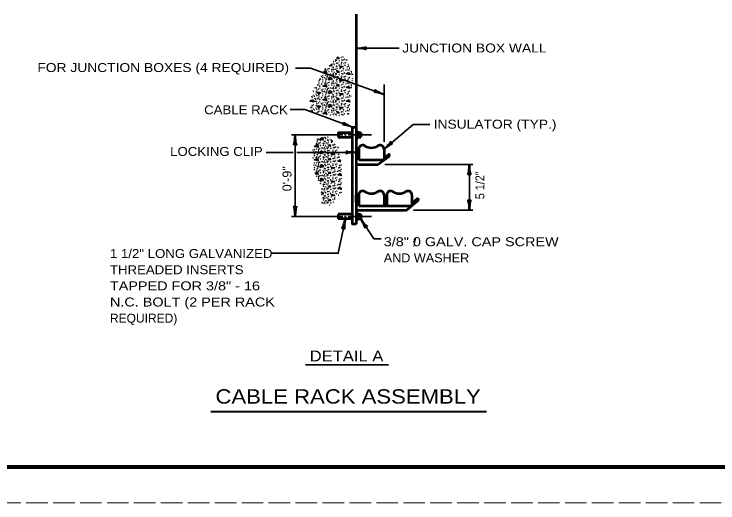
# Model space of a CAD drawing. Extents: x 788 to 1469, y -1 to 439.
# Drawn here: x 1076.7 to 1272.6, y -1 to 135.2 of the extents above; entities that cross this region are included whole.
import ezdxf

# ---------------------------------------------------------------- set-up
doc = ezdxf.new("R2010")
doc.units = 0
doc.linetypes.add('LONG_DASHED', pattern=[7.5, 6, -1.5])
doc.layers.add('1', color=7, linetype='Continuous', lineweight=35)
doc.layers.add('61', color=7, linetype='Continuous', lineweight=35)

msp = doc.modelspace()

# ---------------------------------------------------------------- linework, layer by layer
at = {"layer": '1', "lineweight": 53}
for p, q in [((1171.893, 135.206), (1171.893, 103.706)), ((1166.893, 102.206), (1170.893, 102.206)), ((1166.893, 102.206), (1166.893, 100.956)), ((1171.893, 103.706), (1171.893, 94.98)), ((1171.893, 102.581), (1172.393, 102.581)), ((1172.393, 102.581), (1172.393, 100.581)), ((1172.393, 102.206), (1173.143, 102.206)), ((1173.143, 102.206), (1173.143, 100.956)), ((1166.893, 100.956), (1170.893, 100.956)), ((1171.893, 100.581), (1172.393, 100.581)), ((1172.393, 100.956), (1173.143, 100.956)), ((1172.643, 97.581), (1172.643, 94.581)), ((1179.643, 97.581), (1179.643, 94.581)), ((1171.893, 95.581), (1171.893, 82.831)), ((1172.643, 94.581), (1179.643, 94.581)), ((1177.893, 93.331), (1181.271, 95.743)), ((1171.893, 93.331), (1177.893, 93.331)), ((1172.643, 84.831), (1172.643, 81.831)), ((1179.643, 84.831), (1179.643, 81.831)), ((1180.393, 84.831), (1180.393, 81.831)), ((1187.393, 84.831), (1187.393, 81.831)), ((1171.893, 82.831), (1171.893, 76.706)), ((1179.643, 82.581), (1180.393, 82.581)), ((1170.893, 79.456), (1166.893, 79.456)), ((1166.893, 79.456), (1166.893, 78.206)), ((1172.393, 79.831), (1171.893, 79.831)), ((1172.393, 79.831), (1172.393, 77.831)), ((1172.393, 79.456), (1173.143, 79.456)), ((1173.143, 79.456), (1173.143, 78.206)), ((1170.893, 78.206), (1166.893, 78.206)), ((1172.393, 77.831), (1171.893, 77.831)), ((1172.393, 78.206), (1173.143, 78.206))]:
    msp.add_line(p, q, dxfattribs=at)
at = {"layer": '1'}
for p, q in [((1171.893, 125.706), (1183.893, 125.706)), ((1161.461, 116.472), (1161.461, 116.472)), ((1179.643, 99.581), (1179.643, 115.581)), ((1169.821, 107.532), (1169.381, 107.292)), ((1169.881, 107.397), (1169.781, 107.552)), ((1153.893, 101.581), (1168.143, 101.581)), ((1154.893, 101.581), (1154.893, 78.831)), ((1164.826, 100.12), (1165.152, 100.083)), ((1168.643, 101.581), (1169.143, 101.581)), ((1169.643, 101.581), (1176.143, 101.581)), ((1154.393, 96.686), (1146.825, 96.686)), ((1171.893, 96.686), (1155.393, 96.686)), ((1167.569, 94.327), (1167.406, 94.581)), ((1179.893, 93.331), (1204.393, 93.331)), ((1203.393, 93.331), (1203.393, 80.581)), ((1161.186, 91.141), (1160.426, 90.833)), ((1187.893, 80.581), (1204.393, 80.581)), ((1153.893, 78.831), (1168.143, 78.831)), ((1168.643, 78.831), (1169.143, 78.831)), ((1169.643, 78.831), (1176.143, 78.831)), ((1157.769, 37.483), (1180.923, 37.483))]:
    msp.add_line(p, q, dxfattribs=at)
at = {"layer": '1', "lineweight": 40}
msp.add_line((1131.448, 24.479), (1208.207, 24.479), dxfattribs=at)
at = {"layer": '1'}
for points in [[(1166.921, 123.252), (1166.541, 122.852), (1167.121, 122.812), (1166.921, 123.212)], [(1169.31, 122.453), (1169.161, 122.372), (1169.39, 122.33)], [(1179.643, 112.819), (1159.152, 120.163), (1155.011, 120.163)], [(1164.854, 121.236), (1165.141, 121.072), (1164.363, 120.691)], [(1163.561, 119.312), (1162.621, 118.932), (1163.661, 118.812), (1163.561, 119.272)], [(1164.441, 117.672), (1165.141, 117.272), (1164.281, 116.852), (1164.401, 117.692)], [(1166.921, 119.452), (1166.541, 119.052), (1167.121, 119.012), (1166.921, 119.412)], [(1169.821, 118.932), (1169.161, 118.572), (1170.141, 118.392), (1169.781, 118.952)], [(1161.708, 117.172), (1162.001, 117.112), (1161.496, 116.57)], [(1166.921, 115.652), (1166.541, 115.252), (1167.121, 115.212), (1166.921, 115.612)], [(1163.561, 115.512), (1162.621, 115.132), (1163.661, 115.012), (1163.561, 115.472)], [(1164.441, 113.872), (1165.141, 113.472), (1164.281, 113.052), (1164.401, 113.892)], [(1169.821, 115.132), (1169.161, 114.772), (1170.141, 114.592), (1169.781, 115.152)], [(1161.461, 112.672), (1161.221, 113.472), (1162.001, 113.312), (1161.441, 112.712)], [(1163.561, 111.712), (1162.621, 111.332), (1163.661, 111.212), (1163.561, 111.672)], [(1166.921, 111.852), (1166.541, 111.452), (1167.121, 111.412), (1166.921, 111.812)], [(1159.741, 111.332), (1159.081, 110.972), (1160.061, 110.792), (1159.701, 111.352)], [(1164.441, 110.072), (1165.141, 109.672), (1164.281, 109.252), (1164.401, 110.092)], [(1169.821, 111.332), (1169.161, 110.972), (1170.141, 110.792), (1169.781, 111.352)], [(1170.893, 103.706), (1157.61, 108.629), (1153.469, 108.629)], [(1161.461, 108.872), (1161.221, 109.672), (1162.001, 109.512), (1161.441, 108.912)], [(1163.561, 107.912), (1162.621, 107.532), (1163.661, 107.412), (1163.561, 107.872)], [(1166.921, 108.052), (1166.541, 107.652), (1167.121, 107.612), (1166.921, 108.012)], [(1179.643, 97.581), (1187.734, 104.486), (1192.363, 104.486)], [(1162.274, 100.782), (1162.766, 100.501), (1161.906, 100.081), (1161.996, 100.71)], [(1165.417, 99.842), (1165.186, 99.76), (1164.826, 100.12)], [(1161.186, 98.74), (1160.246, 98.361), (1161.286, 98.24), (1161.186, 98.7)], [(1164.546, 98.88), (1164.166, 98.48), (1164.746, 98.441), (1164.546, 98.84)], [(1166.96, 98.095), (1166.786, 98.001), (1166.981, 97.965)], [(1159.578, 96.55), (1159.626, 96.54), (1159.571, 96.481)], [(1162.066, 97.1), (1162.766, 96.7), (1161.906, 96.281), (1162.026, 97.12)], [(1161.186, 94.941), (1160.246, 94.56), (1161.286, 94.441), (1161.186, 94.9)], [(1164.546, 95.081), (1164.166, 94.68), (1164.746, 94.641), (1164.546, 95.04)], [(1167.446, 94.56), (1166.786, 94.2), (1167.614, 94.048)], [(1162.066, 93.3), (1162.766, 92.9), (1161.906, 92.48), (1162.026, 93.32)], [(1160.473, 90.734), (1161.286, 90.641), (1161.186, 91.1)], [(1164.546, 91.281), (1164.166, 90.88), (1164.746, 90.84), (1164.546, 91.24)], [(1167.446, 90.76), (1166.786, 90.4), (1167.766, 90.221), (1167.406, 90.781)], [(1162.066, 89.501), (1162.766, 89.1), (1161.906, 88.68), (1162.026, 89.52)], [(1164.546, 87.48), (1164.166, 87.081), (1164.746, 87.04), (1164.546, 87.441)], [(1167.446, 86.96), (1166.786, 86.6), (1167.766, 86.421), (1167.406, 86.98)], [(1162.115, 85.673), (1162.766, 85.3), (1162.102, 84.976)], [(1164.546, 83.68), (1164.166, 83.281), (1164.746, 83.24), (1164.546, 83.641)], [(1168.885, 78.206), (1166.887, 68.566), (1148.331, 68.566)], [(1173.143, 78.206), (1176.809, 72.616), (1178.815, 72.616)]]:
    msp.add_lwpolyline(points, dxfattribs=at)
for points in [[(1167.201, 120.692), (1168.241, 120.572), (1167.561, 120.332)], [(1167.201, 116.892), (1168.241, 116.772), (1167.561, 116.532)], [(1167.201, 113.092), (1168.241, 112.972), (1167.561, 112.732)], [(1167.201, 109.292), (1168.241, 109.172), (1167.561, 108.932)], [(1164.826, 96.32), (1165.866, 96.2), (1165.186, 95.96)], [(1171.893, 95.581), (1171.893, 97.581), (1172.643, 97.581), (1172.643, 95.581)], [(1164.826, 92.52), (1165.866, 92.4), (1165.186, 92.16)], [(1164.826, 88.721), (1165.866, 88.6), (1165.186, 88.361)], [(1164.826, 84.921), (1165.866, 84.8), (1165.186, 84.56)]]:
    msp.add_lwpolyline(points, close=True, dxfattribs=at)
at = {"layer": '1', "lineweight": 53}
for points in [[(1171.893, 76.706), (1170.893, 76.706), (1170.893, 103.706), (1171.893, 103.706)], [(1179.643, 95.195), (1180.98, 96.15), (1181.271, 95.743)], [(1171.893, 80.581), (1185.893, 80.581), (1189.314, 83.431)], [(1187.393, 82.482), (1188.994, 83.815), (1189.314, 83.431)], [(1172.643, 81.831), (1179.643, 81.831), (1187.393, 81.831)]]:
    msp.add_lwpolyline(points, dxfattribs=at)
msp.add_lwpolyline([(1171.893, 84.831), (1172.643, 84.831), (1172.643, 82.831), (1171.893, 82.831)], close=True, dxfattribs=at)
at = {"layer": '1'}
for centre in [(1165.611, 122.01), (1166.194, 122.421), (1166.208, 122.102), (1166.367, 121.506), (1166.427, 122.341), (1166.785, 121.559), (1167.209, 122.169), (1167.819, 123.11), (1167.845, 121.665), (1167.925, 122.394), (1168.27, 123.282), (1168.27, 122.354), (1168.588, 122.593), (1168.932, 121.665), (1163.159, 119.602), (1163.372, 119.915), (1163.796, 119.562), (1164.074, 119.888), (1164.352, 120.008), (1165.094, 120.724), (1165.121, 119.655), (1165.134, 119.822), (1165.426, 120.326), (1165.558, 121.453), (1165.624, 119.708), (1165.651, 120.326), (1165.784, 121.161), (1166.115, 119.835), (1166.347, 120.695), (1166.48, 119.522), (1166.573, 120.71), (1166.573, 120.114), (1167.116, 121.042), (1167.382, 120.074), (1167.792, 121.267), (1168.376, 119.995), (1168.535, 121.453), (1168.813, 120.936), (1169.078, 119.575), (1169.409, 120.525), (1169.476, 119.769), (1169.688, 121.161), (1169.727, 120.671), (1169.873, 119.641), (1170.072, 120.127), (1162.232, 117.865), (1162.643, 118.09), (1163.292, 118.183), (1163.69, 118.674), (1163.756, 117.547), (1163.822, 117.852), (1163.928, 118.17), (1164.206, 118.342), (1164.326, 119.191), (1164.737, 118.462), (1165.161, 119.204), (1165.187, 118.316), (1165.505, 118.607), (1165.558, 117.653), (1165.611, 118.21), (1165.837, 119.018), (1166.194, 118.621), (1166.208, 118.302), (1166.367, 117.706), (1166.427, 118.541), (1166.785, 117.759), (1167.209, 118.369), (1167.819, 119.31), (1167.845, 117.865), (1167.925, 118.594), (1168.27, 119.482), (1168.27, 118.554), (1168.535, 117.653), (1168.588, 118.793), (1168.932, 117.865), (1170.496, 119.244), (1170.496, 118.501), (1170.655, 119.032), (1170.88, 118.409), (1161.49, 115.603), (1161.582, 116.128), (1162.271, 115.709), (1162.51, 117.494), (1162.603, 116.34), (1162.669, 116.884), (1163.027, 117.467), (1163.159, 115.802), (1163.372, 116.115), (1163.451, 117.136), (1163.464, 116.619), (1163.743, 117.07), (1163.796, 115.762), (1164.074, 116.088), (1164.352, 116.208), (1165.094, 116.924), (1165.121, 115.855), (1165.134, 116.022), (1165.426, 116.526), (1165.624, 115.908), (1165.651, 116.526), (1165.784, 117.361), (1166.115, 116.035), (1166.347, 116.895), (1166.48, 115.722), (1166.573, 116.91), (1166.573, 116.314), (1167.116, 117.242), (1167.382, 116.274), (1167.792, 117.467), (1168.27, 115.682), (1168.376, 116.195), (1168.813, 117.136), (1169.078, 115.775), (1169.409, 116.725), (1169.476, 115.969), (1169.688, 117.361), (1169.727, 116.871), (1169.873, 115.841), (1170.072, 116.327), (1170.098, 117.534), (1170.43, 116.128), (1160.018, 113.734), (1160.8, 114.609), (1160.92, 114.038), (1161.463, 114.277), (1161.715, 115.139), (1161.768, 115.139), (1161.834, 114.555), (1162.232, 114.065), (1162.51, 113.694), (1162.643, 114.29), (1163.027, 113.667), (1163.292, 114.383), (1163.69, 114.874), (1163.756, 113.747), (1163.822, 114.052), (1163.928, 114.37), (1164.206, 114.542), (1164.326, 115.391), (1164.737, 114.662), (1165.161, 115.404), (1165.187, 114.516), (1165.505, 114.807), (1165.558, 113.853), (1165.611, 114.41), (1165.837, 115.218), (1166.194, 114.821), (1166.208, 114.502), (1166.367, 113.906), (1166.427, 114.741), (1166.785, 113.959), (1167.209, 114.569), (1167.792, 113.667), (1167.819, 115.51), (1167.845, 114.065), (1167.925, 114.794), (1168.27, 114.754), (1168.535, 113.853), (1168.588, 114.993), (1168.932, 114.065), (1170.098, 113.734), (1170.496, 115.444), (1170.496, 114.701), (1170.655, 115.232), (1159.793, 112.041), (1159.992, 112.527), (1160.35, 112.328), (1160.747, 112.898), (1160.787, 113.495), (1160.933, 112.474), (1161.49, 111.803), (1161.582, 112.328), (1162.271, 111.909), (1162.603, 112.54), (1162.669, 113.084), (1163.159, 112.002), (1163.372, 112.315), (1163.451, 113.336), (1163.464, 112.819), (1163.743, 113.27), (1163.796, 111.962), (1164.074, 112.288), (1164.352, 112.408), (1165.094, 113.124), (1165.121, 112.055), (1165.134, 112.222), (1165.426, 112.726), (1165.624, 112.108), (1165.651, 112.726), (1165.784, 113.561), (1166.115, 112.235), (1166.347, 113.095), (1166.48, 111.922), (1166.573, 113.11), (1166.573, 112.514), (1167.116, 113.442), (1167.382, 112.474), (1167.819, 111.71), (1168.27, 111.882), (1168.376, 112.395), (1168.813, 113.336), (1169.078, 111.975), (1169.409, 112.925), (1169.476, 112.169), (1169.688, 113.561), (1169.727, 113.071), (1169.873, 112.041), (1170.072, 112.527), (1170.43, 112.328), (1159.608, 109.761), (1160.018, 109.934), (1160.416, 111.644), (1160.416, 110.901), (1160.575, 111.432), (1160.8, 110.809), (1160.92, 110.238), (1161.092, 111.644), (1161.463, 110.477), (1161.715, 111.339), (1161.768, 111.339), (1161.834, 110.755), (1162.232, 110.265), (1162.51, 109.894), (1162.643, 110.49), (1163.027, 109.867), (1163.292, 110.583), (1163.69, 111.074), (1163.756, 109.947), (1163.822, 110.252), (1163.928, 110.57), (1164.206, 110.742), (1164.326, 111.591), (1164.737, 110.862), (1165.161, 111.604), (1165.187, 110.716), (1165.505, 111.007), (1165.558, 110.053), (1165.611, 110.61), (1165.784, 109.761), (1165.837, 111.418), (1166.194, 111.021), (1166.208, 110.702), (1166.367, 110.106), (1166.427, 110.941), (1166.785, 110.159), (1167.209, 110.769), (1167.792, 109.867), (1167.845, 110.265), (1167.925, 110.994), (1168.27, 110.954), (1168.535, 110.053), (1168.588, 111.193), (1168.932, 110.265), (1169.688, 109.761), (1170.098, 109.934), (1159.329, 109.125), (1159.396, 108.369), (1159.647, 109.271), (1159.793, 108.241), (1159.992, 108.727), (1160.35, 108.528), (1160.747, 109.098), (1160.787, 109.695), (1160.933, 108.674), (1161.49, 108.003), (1161.582, 108.528), (1162.271, 108.109), (1162.603, 108.74), (1162.669, 109.284), (1163.159, 108.202), (1163.372, 108.515), (1163.451, 109.536), (1163.464, 109.019), (1163.743, 109.47), (1163.796, 108.162), (1164.074, 108.488), (1164.326, 107.791), (1164.352, 108.608), (1165.094, 109.324), (1165.121, 108.255), (1165.134, 108.422), (1165.161, 107.804), (1165.426, 108.926), (1165.624, 108.308), (1165.651, 108.926), (1166.115, 108.435), (1166.347, 109.295), (1166.48, 108.122), (1166.573, 109.31), (1166.573, 108.714), (1167.116, 109.642), (1167.382, 108.674), (1167.819, 107.91), (1168.27, 108.082), (1168.376, 108.595), (1168.813, 109.536), (1169.078, 108.175), (1169.409, 109.125), (1169.476, 108.369), (1169.727, 109.271), (1169.873, 108.241), (1170.072, 108.727), (1163.69, 107.274), (1164.737, 107.062), (1165.505, 107.207), (1165.837, 107.618), (1166.194, 107.221), (1166.427, 107.141), (1167.209, 106.969), (1167.925, 107.194), (1168.27, 107.154), (1168.588, 107.393), (1161.076, 100.365), (1161.367, 100.298), (1162.719, 100.153), (1163.183, 100.882), (1163.408, 100.59), (1163.972, 100.124), (1163.991, 100.935), (1164.198, 100.139), (1160.784, 99.031), (1160.996, 99.344), (1161.089, 99.848), (1161.314, 98.102), (1161.42, 98.991), (1161.699, 99.317), (1161.95, 98.62), (1161.977, 99.437), (1162.746, 99.084), (1162.759, 99.251), (1162.785, 98.633), (1163.05, 99.755), (1163.13, 98.036), (1163.249, 99.137), (1163.276, 99.755), (1163.461, 98.447), (1163.74, 99.264), (1163.819, 98.049), (1164.052, 97.97), (1164.105, 98.951), (1164.198, 99.543), (1165.006, 99.503), (1165.444, 98.739), (1165.55, 98.023), (1165.894, 98.911), (1165.894, 97.983), (1166.212, 98.222), (1159.856, 97.294), (1160.135, 96.923), (1160.267, 97.519), (1160.294, 96.313), (1160.652, 96.896), (1160.917, 97.612), (1161.076, 96.565), (1161.089, 96.048), (1161.367, 96.498), (1161.38, 96.976), (1161.447, 97.281), (1161.553, 97.599), (1161.831, 97.771), (1162.361, 97.89), (1162.719, 96.353), (1162.812, 97.745), (1163.183, 97.082), (1163.236, 97.638), (1163.408, 96.79), (1163.832, 97.731), (1163.972, 96.324), (1163.991, 97.135), (1164.198, 96.339), (1164.41, 97.188), (1164.741, 96.671), (1164.834, 97.798), (1165.417, 96.896), (1165.47, 97.294), (1166.159, 97.082), (1166.438, 96.565), (1166.557, 97.294), (1167.034, 96.154), (1159.896, 95.138), (1160.227, 95.769), (1160.784, 95.231), (1160.996, 95.544), (1161.314, 94.302), (1161.42, 95.191), (1161.699, 95.517), (1161.95, 94.82), (1161.977, 95.637), (1162.361, 94.09), (1162.746, 95.284), (1162.759, 95.451), (1162.785, 94.833), (1163.05, 95.955), (1163.13, 94.236), (1163.249, 95.337), (1163.276, 95.955), (1163.461, 94.647), (1163.74, 95.464), (1163.819, 94.249), (1164.052, 94.17), (1164.105, 95.151), (1164.198, 95.743), (1165.006, 95.703), (1165.444, 94.939), (1165.55, 94.223), (1165.894, 95.111), (1165.894, 94.183), (1166, 95.623), (1166.212, 94.422), (1166.703, 95.204), (1167.1, 95.398), (1160.135, 93.123), (1160.267, 93.719), (1160.294, 92.513), (1160.652, 93.096), (1160.917, 93.812), (1161.076, 92.765), (1161.089, 92.248), (1161.367, 92.698), (1161.38, 93.176), (1161.447, 93.481), (1161.553, 93.799), (1161.831, 93.971), (1162.719, 92.553), (1162.812, 93.945), (1163.05, 92.155), (1163.183, 93.282), (1163.236, 93.838), (1163.276, 92.155), (1163.408, 92.99), (1163.832, 93.931), (1163.972, 92.524), (1163.991, 93.335), (1164.198, 92.539), (1164.41, 93.388), (1164.741, 92.871), (1164.834, 93.998), (1165.417, 93.096), (1165.47, 93.494), (1166.159, 93.282), (1166.438, 92.765), (1166.557, 93.494), (1167.034, 92.354), (1167.312, 92.99), (1167.352, 92.5), (1167.723, 93.162), (1160.227, 91.969), (1160.784, 91.431), (1160.996, 91.744), (1161.314, 90.502), (1161.42, 91.391), (1161.699, 91.717), (1161.831, 90.171), (1161.95, 91.02), (1161.977, 91.837), (1162.361, 90.29), (1162.746, 91.484), (1162.759, 91.651), (1162.785, 91.033), (1162.812, 90.145), (1163.13, 90.436), (1163.249, 91.537), (1163.461, 90.847), (1163.74, 91.664), (1163.819, 90.449), (1163.832, 90.131), (1164.052, 90.37), (1164.105, 91.351), (1164.198, 91.943), (1164.834, 90.198), (1165.006, 91.903), (1165.444, 91.139), (1165.55, 90.423), (1165.894, 91.311), (1165.894, 90.383), (1166, 91.823), (1166.212, 90.622), (1166.703, 91.404), (1167.1, 91.598), (1167.498, 91.47), (1167.697, 91.956), (1160.917, 90.012), (1161.38, 89.376), (1161.447, 89.681), (1161.553, 89.999), (1162.719, 88.753), (1163.05, 88.355), (1163.183, 89.482), (1163.236, 90.038), (1163.276, 88.355), (1163.408, 89.19), (1163.972, 88.724), (1163.991, 89.535), (1164.198, 88.739), (1164.41, 89.588), (1164.741, 89.071), (1165.417, 89.296), (1165.47, 89.694), (1166.159, 89.482), (1166.438, 88.965), (1166.557, 89.694), (1167.034, 88.554), (1167.312, 89.19), (1167.352, 88.7), (1167.697, 88.156), (1167.723, 89.362), (1161.977, 88.037), (1162.361, 86.49), (1162.746, 87.684), (1162.759, 87.851), (1162.785, 87.233), (1162.812, 86.345), (1163.13, 86.636), (1163.236, 86.238), (1163.249, 87.737), (1163.461, 87.047), (1163.74, 87.864), (1163.819, 86.649), (1163.832, 86.331), (1164.052, 86.57), (1164.105, 87.551), (1164.198, 88.143), (1164.834, 86.398), (1165.006, 88.103), (1165.444, 87.339), (1165.55, 86.623), (1165.894, 87.511), (1165.894, 86.583), (1166, 88.023), (1166.212, 86.822), (1166.703, 87.604), (1167.1, 87.798), (1167.498, 87.67), (1162.719, 84.953), (1163.05, 84.555), (1163.183, 85.682), (1163.276, 84.555), (1163.408, 85.39), (1163.972, 84.924), (1163.991, 85.735), (1164.198, 84.939), (1164.198, 84.343), (1164.41, 85.788), (1164.741, 85.271), (1165.006, 84.303), (1165.417, 85.496), (1165.47, 85.894), (1166.159, 85.682), (1166.438, 85.165), (1166.557, 85.894), (1167.034, 84.754), (1167.312, 85.39), (1167.723, 85.562), (1162.361, 82.69), (1162.746, 83.884), (1162.759, 84.051), (1162.785, 83.433), (1162.812, 82.545), (1163.13, 82.836), (1163.236, 82.438), (1163.249, 83.937), (1163.461, 83.247), (1163.74, 84.064), (1163.819, 82.849), (1163.832, 82.531), (1164.052, 82.77), (1164.105, 83.751), (1164.834, 82.598), (1165.444, 83.539), (1165.55, 82.823), (1165.894, 83.711), (1166, 84.223)]:
    msp.add_circle(centre, 0.0265, dxfattribs=at)
for centre, start, end in [((1170.827, 116.698), 81.7766, 271.39236), ((1170.867, 117.295), 90.7068, 262.46216), ((1160.416, 114.701), 230.82288, 46.82584), ((1161.092, 115.444), 183.01325, 94.63547), ((1159.396, 112.169), 206.21163, 115.66112), ((1161.092, 107.844), 291.77182, 216.03601), ((1164.741, 100.471), 163.57975, 292.03289), ((1161.367, 88.898), 257.94855, 153.06656), ((1164.41, 81.988), 20.334, 145.41282)]:
    msp.add_arc(centre, 0.0265, start, end, dxfattribs=at)
at = {"layer": '1', "lineweight": 53}
for centre, radius, start, end in [((1173.709, 97.607), 1.066, 65.99256, 181.38757), ((1176.143, 101.594), 3.617, 236.42696, 303.57304), ((1178.577, 97.607), 1.066, 358.61243, 114.00744), ((1173.709, 84.857), 1.066, 65.99256, 181.38757), ((1176.143, 88.844), 3.617, 236.42696, 303.57304), ((1178.577, 84.857), 1.066, 358.61243, 114.00744), ((1181.459, 84.857), 1.066, 65.99256, 181.38757), ((1183.893, 88.844), 3.617, 236.42696, 303.57304), ((1186.327, 84.857), 1.066, 358.61243, 114.00744)]:
    msp.add_arc(centre, radius, start, end, dxfattribs=at)
at = {"layer": '1', "lineweight": 40}
for centre, major_axis, ratio, start_param, end_param in [((1172.984, 125.982), (-1.786, -0.156), 0.122415, 0.8963533, 3.1415927), ((1172.984, 125.982), (-1.786, -0.156), 0.122415, 0.8963533, 3.1415927), ((1173.014, 125.494), (-1.756, 0.176), 0.07063, 3.1407148, 5.41811), ((1173.014, 125.494), (-1.756, 0.176), 0.07063, 3.1407148, 5.41811), ((1178.66, 113.396), (-1.594, 0.758), 0.07063, 6.2823074, 8.5597026), ((1178.66, 113.396), (-1.594, 0.758), 0.07063, 6.2823074, 8.5597026), ((1178.523, 112.927), (1.734, -0.455), 0.122415, 0.8963533, 3.1415927), ((1178.523, 112.927), (1.734, -0.455), 0.122415, 0.8963533, 3.1415927), ((1169.774, 103.826), (1.729, -0.474), 0.122415, 0.8963533, 3.1415927), ((1169.774, 103.826), (1.729, -0.474), 0.122415, 0.8963533, 3.1415927), ((1169.916, 104.294), (-1.586, 0.775), 0.07063, 6.2823074, 8.5597026), ((1169.916, 104.294), (-1.586, 0.775), 0.07063, 6.2823074, 8.5597026), ((1154.682, 100.46), (0.176, 1.756), 0.07063, 3.1407148, 5.41811), ((1154.682, 100.46), (0.176, 1.756), 0.07063, 3.1407148, 5.41811), ((1155.169, 100.49), (-0.156, 1.786), 0.122415, 0.8963533, 3.1415927), ((1155.169, 100.49), (-0.156, 1.786), 0.122415, 0.8963533, 3.1415927), ((1180.294, 98.499), (-1.257, -1.278), 0.122415, 0.8963533, 3.1415927), ((1180.633, 98.147), (-1.45, -1.007), 0.07063, 3.1407148, 5.41811), ((1170.802, 96.41), (1.786, 0.156), 0.122415, 0.8963533, 3.1415927), ((1170.802, 96.41), (1.786, 0.156), 0.122415, 0.8963533, 3.1415927), ((1170.773, 96.898), (1.756, -0.176), 0.07063, 3.1407148, 5.41811), ((1170.773, 96.898), (1.756, -0.176), 0.07063, 3.1407148, 5.41811), ((1203.182, 92.21), (0.176, 1.756), 0.07063, 3.1407148, 5.41811), ((1203.182, 92.21), (0.176, 1.756), 0.07063, 3.1407148, 5.41811), ((1203.669, 92.24), (-0.156, 1.786), 0.122415, 0.8963533, 3.1415927), ((1203.669, 92.24), (-0.156, 1.786), 0.122415, 0.8963533, 3.1415927), ((1203.117, 81.672), (0.156, -1.786), 0.122415, 0.8963533, 3.1415927), ((1203.117, 81.672), (0.156, -1.786), 0.122415, 0.8963533, 3.1415927), ((1203.605, 81.701), (-0.176, -1.756), 0.07063, 3.1407148, 5.41811), ((1203.605, 81.701), (-0.176, -1.756), 0.07063, 3.1407148, 5.41811), ((1154.617, 79.922), (0.156, -1.786), 0.122415, 0.8963533, 3.1415927), ((1155.105, 79.951), (-0.176, -1.756), 0.07063, 3.1407148, 5.41811), ((1168.451, 77.152), (-0.529, -1.684), 0.07063, 6.2823074, 8.5597026), ((1168.451, 77.152), (-0.529, -1.684), 0.07063, 6.2823074, 8.5597026), ((1168.934, 77.081), (0.21, 1.78), 0.122415, 0.8963533, 3.1415927), ((1168.934, 77.081), (0.21, 1.78), 0.122415, 0.8963533, 3.1415927), ((1173.581, 77.153), (-0.816, 1.565), 0.07063, 3.1407148, 5.41811), ((1173.973, 77.445), (-1.11, 1.408), 0.122415, 0.8963533, 3.1415927)]:
    msp.add_ellipse(centre, major_axis=major_axis, ratio=ratio, start_param=start_param, end_param=end_param, dxfattribs=at)
at = {"layer": '61', "lineweight": 158}
msp.add_line((1457.587, 9.036), (818.527, 9.056), dxfattribs=at)
at = {"layer": '61', "linetype": 'LONG_DASHED', "lineweight": 13}
msp.add_line((1468.527, -0.944), (788.467, -0.964), dxfattribs=at)

# ---------------------------------------------------------------- texts
at = {"layer": '1'}
for s, height, width, p in [('JUNCTION BOX WALL', 2.5, 1.15, (1184.726, 124.502)), ('FOR JUNCTION BOXES (4 REQUIRED)', 2.5, 1.15, (1083.137, 119.055)), ('CABLE RACK', 2.5, 1.1, (1129.561, 107.302)), ('INSULATOR (TYP.)', 2.5, 1.15, (1193.466, 103.288)), ('LOCKING CLIP', 2.5, 1.1, (1120.104, 95.692)), ('3/8" 0 GALV. CAP SCREW', 2.5, 1.2, (1179.567, 70.546)), ('1 1/2" LONG GALVANIZED', 2.5, 1.1, (1103.34, 67.249)), ('AND WASHER', 2.5, 1.05, (1179.567, 66.046)), ('THREADED INSERTS', 2.5, 1.1, (1103.34, 62.749)), ('TAPPED FOR 3/8" - 16', 2.5, 1.2, (1103.34, 58.249)), ('N.C. BOLT (2 PER RACK', 2.5, 1.2, (1103.34, 53.749)), ('DETAIL A', 3, 1.15, (1158.948, 38.466)), ('CABLE RACK ASSEMBLY', 4, 1.15, (1132.728, 26.699))]:
    msp.add_text(s, height=height, dxfattribs=dict(at, width=width)).set_placement(p)
for s, width, p in [('0\'-9"', 1.05, (1153.88, 85.833)), ('5 1/2"', 0.9, (1207.599, 83.634))]:
    msp.add_text(s, height=2.5, rotation=90, dxfattribs=dict(at, width=width)).set_placement(p)
for s, p in [('/', (1187.777, 70.455)), ('REQUIRED)', (1103.34, 49.249))]:
    msp.add_text(s, height=2.5, dxfattribs=at).set_placement(p)

doc.saveas('drawing.dxf')
